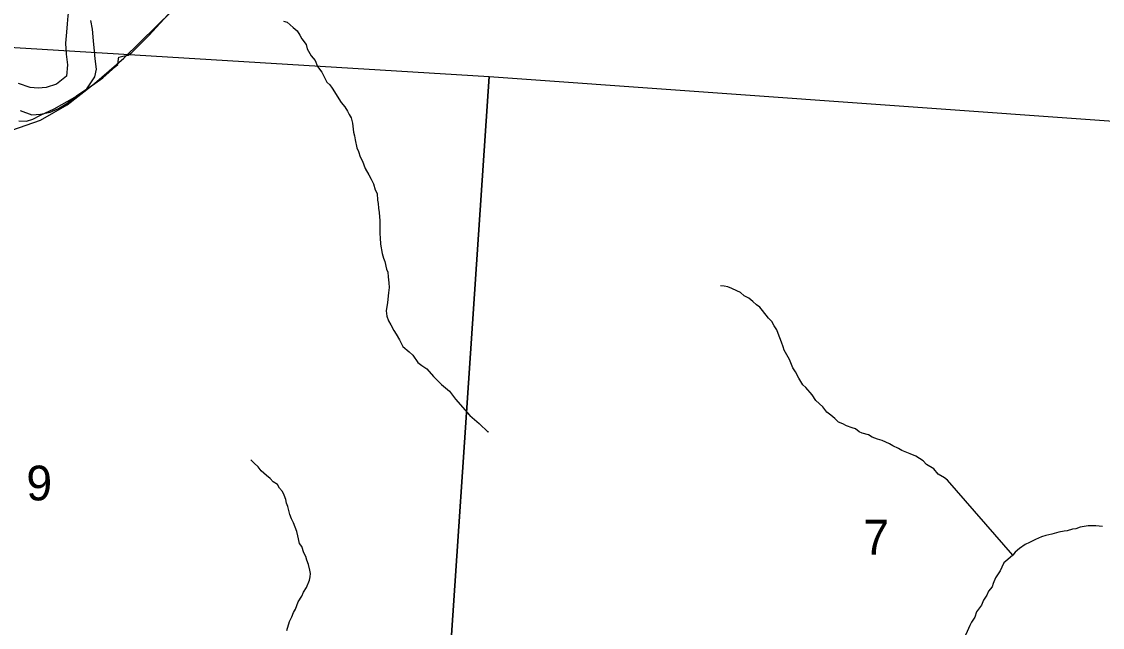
# Model space of a CAD drawing. Extents: x 0 to 44, y -23.8 to 22.
# Drawn here: x 6.018 to 7.321, y 18.843 to 19.573 of the extents above; entities that cross this region are included whole.
import ezdxf

# ---------------------------------------------------------------- set-up
doc = ezdxf.new("R2010")
doc.units = 0
for name, color, linetype in [('GM_X_Minor_River', 7, 'Continuous'), ('GM_X_Rail_Line', 7, 'Continuous'), ('GM_X_Section', 7, 'Continuous'), ('GM_X_Section_Text', 7, 'Continuous'), ('GM_X_Township_Road', 7, 'Continuous')]:
    doc.layers.add(name, color=color, linetype=linetype)

msp = doc.modelspace()

# ---------------------------------------------------------------- linework, layer by layer
at = {"layer": 'GM_X_Minor_River'}
for points in [[(6.0896, 19.6402), (6.0854, 19.6265), (6.0819, 19.617), (6.0781, 19.6045), (6.0758, 19.5942), (6.0739, 19.5802), (6.0732, 19.5706), (6.0724, 19.5604), (6.0712, 19.5471), (6.072, 19.5342), (6.0735, 19.5212), (6.0724, 19.5075), (6.0602, 19.4977), (6.048, 19.4939), (6.0381, 19.4931), (6.0286, 19.4939), (6.0146, 19.4985)], [(6.0164, 19.466), (6.0305, 19.4607), (6.0411, 19.4615), (6.0525, 19.4641), (6.0628, 19.4683), (6.0727, 19.4747), (6.086, 19.485), (6.097, 19.4922), (6.1065, 19.5066), (6.1084, 19.5161), (6.1069, 19.5283), (6.1062, 19.5378), (6.105, 19.55), (6.1039, 19.564), (6.1016, 19.5747)], [(6.3342, 19.5736), (6.3384, 19.5724), (6.3455, 19.5662), (6.3504, 19.562), (6.3537, 19.557), (6.3563, 19.5524), (6.3612, 19.5455), (6.3627, 19.5405), (6.3675, 19.5321), (6.372, 19.5264), (6.3749, 19.5191), (6.3802, 19.5122), (6.3861, 19.5003), (6.3899, 19.4969), (6.3925, 19.493), (6.4036, 19.4758), (6.4078, 19.4704), (6.4111, 19.4651), (6.4133, 19.4612), (6.4156, 19.4574), (6.4174, 19.4509), (6.4184, 19.4399), (6.4195, 19.4357), (6.4206, 19.4308), (6.4224, 19.4209), (6.4246, 19.4166), (6.4264, 19.4102), (6.4294, 19.4048), (6.4323, 19.396), (6.4368, 19.3884), (6.4398, 19.3834), (6.4427, 19.3777), (6.4445, 19.3704), (6.4468, 19.3662), (6.4474, 19.3578), (6.4481, 19.354), (6.4485, 19.3483), (6.4492, 19.343), (6.4502, 19.3331), (6.45, 19.3175), (6.4507, 19.3126), (6.451, 19.305), (6.4531, 19.2936), (6.4546, 19.2882), (6.4561, 19.284), (6.4582, 19.2749), (6.4597, 19.271), (6.4604, 19.2657), (6.4611, 19.2585), (6.4614, 19.2528), (6.4606, 19.2463), (6.4593, 19.2346), (6.458, 19.2247), (6.4587, 19.2182), (6.4605, 19.2125), (6.4635, 19.2075), (6.4669, 19.201), (6.4698, 19.1964), (6.4739, 19.1896), (6.478, 19.1815), (6.4855, 19.175), (6.49, 19.1711)], [(7.2134, 18.9298), (7.1348, 19.0205), (7.131, 19.0232), (7.1235, 19.0278), (7.1182, 19.034), (7.1092, 19.0394), (7.1054, 19.0436), (7.0964, 19.0495), (7.0896, 19.0522), (7.0794, 19.0561), (7.0756, 19.0585), (7.0685, 19.0616), (7.0647, 19.0643), (7.056, 19.0682), (7.0504, 19.0698), (7.0439, 19.0722), (7.0394, 19.0752), (7.0319, 19.0772), (7.0281, 19.0788), (7.0236, 19.0823), (7.0198, 19.0835), (7.013, 19.0858), (7.0085, 19.0882), (7.0032, 19.0905), (6.9987, 19.0948), (6.9938, 19.0986), (6.9893, 19.1025), (6.9844, 19.109), (6.9758, 19.1163), (6.9713, 19.1232), (6.9638, 19.1321), (6.9601, 19.1355), (6.9552, 19.1432), (6.9515, 19.1512), (6.9482, 19.1558), (6.9441, 19.1657), (6.9378, 19.1772), (6.9363, 19.181), (6.9345, 19.1868), (6.9326, 19.1921), (6.9304, 19.1971), (6.929, 19.2017), (6.9256, 19.2066), (6.923, 19.2116), (6.9189, 19.2158), (6.9114, 19.2251), (6.9084, 19.2289), (6.9043, 19.2316), (6.8998, 19.2358), (6.8949, 19.2397), (6.8896, 19.2428), (6.8851, 19.2467), (6.8806, 19.2486), (6.8745, 19.2514), (6.8696, 19.2533), (6.8654, 19.2541), (6.8609, 19.2546)], [(6.49, 19.1711), (6.496, 19.1623), (6.5009, 19.1588), (6.5069, 19.1546), (6.5148, 19.1453), (6.5215, 19.1388), (6.5247, 19.1356)], [(6.5247, 19.1356), (6.5343, 19.1277), (6.5415, 19.1181), (6.5587, 19.0983), (6.57, 19.0887), (6.5806, 19.0784), (6.5813, 19.0795)], [(6.3382, 18.839), (6.3414, 18.85), (6.3441, 18.8557), (6.3461, 18.861), (6.3484, 18.8648), (6.3519, 18.8738), (6.3562, 18.8806), (6.3581, 18.8855), (6.3616, 18.8908), (6.3655, 18.8999), (6.3663, 18.9037), (6.3664, 18.9078), (6.3656, 18.912), (6.3642, 18.9185), (6.362, 18.9239), (6.3609, 18.9284), (6.3587, 18.9326), (6.3561, 18.9403), (6.3535, 18.9441), (6.3513, 18.9532), (6.3499, 18.9586), (6.348, 18.9636), (6.3462, 18.9689), (6.3436, 18.9739), (6.3418, 18.9788), (6.3403, 18.9838), (6.3392, 18.9887), (6.3377, 18.9926), (6.337, 18.9971), (6.3348, 19.0021), (6.333, 19.0067), (6.3292, 19.0109), (6.3266, 19.0151), (6.3217, 19.0182), (6.318, 19.0224), (6.3135, 19.0259), (6.3071, 19.0317), (6.3033, 19.0363), (6.2985, 19.0409), (6.2947, 19.0448)], [(7.3215, 18.9645), (7.3136, 18.9654), (7.309, 18.9655), (7.3041, 18.9655), (7.2946, 18.9637), (7.2893, 18.9619), (7.2855, 18.9612), (7.279, 18.9594), (7.2752, 18.9587), (7.2687, 18.9576), (7.2604, 18.9554), (7.2531, 18.9536), (7.2478, 18.9522), (7.2406, 18.9488), (7.2333, 18.9451), (7.2283, 18.9429), (7.2215, 18.9381), (7.2161, 18.9336), (7.2134, 18.9298), (7.2073, 18.9246), (7.2027, 18.9208), (7.2, 18.9155), (7.198, 18.911), (7.1926, 18.9027), (7.1895, 18.8959), (7.1883, 18.8917), (7.1841, 18.8865), (7.1821, 18.8816), (7.1779, 18.8755), (7.1755, 18.8695), (7.1697, 18.8616)], [(7.1697, 18.8616), (7.1674, 18.8552), (7.1635, 18.8491), (7.1616, 18.8453), (7.1569, 18.8344), (7.1534, 18.8299), (7.1492, 18.825), (7.1457, 18.8186), (7.1388, 18.8088), (7.1334, 18.8039), (7.1288, 18.7983), (7.1226, 18.7919), (7.1184, 18.7874), (7.1172, 18.7813), (7.1118, 18.7768), (7.108, 18.7734), (7.1042, 18.7705)]]:
    msp.add_lwpolyline(points, dxfattribs=at)
at = {"layer": 'GM_X_Rail_Line'}
msp.add_lwpolyline([(6.0065, 19.4423), (6.0411, 19.4544), (6.0732, 19.4729), (6.1062, 19.4986), (6.1416, 19.5292), (6.395, 19.7779), (6.6878, 20.0692), (6.7143, 20.0982), (6.7384, 20.1312), (6.7521, 20.1626), (6.7752, 20.2051), (6.7849, 20.2473), (6.7922, 20.2869), (6.7971, 20.3238), (6.7954, 20.3554), (6.7929, 20.385), (6.7849, 20.432), (6.7699, 20.4736), (6.7338, 20.5421), (6.7166, 20.5611)], dxfattribs=at)
at = {"layer": 'GM_X_Section'}
for points in [[(5.5628, 19.5693), (6.5821, 19.5069), (6.5134, 18.488), (5.5009, 18.5537)], [(6.5821, 19.5069), (7.5875, 19.4351), (7.5123, 18.4238), (6.5134, 18.488)]]:
    msp.add_lwpolyline(points, close=True, dxfattribs=at)
at = {"layer": 'GM_X_Township_Road'}
for points in [[(6.1316, 19.519), (6.1344, 19.5215), (6.1349, 19.5283), (6.1356, 19.5304), (6.1403, 19.5317), (6.1467, 19.5329), (6.151, 19.536), (6.1717, 19.5565), (6.199, 19.5864)], [(6.0151, 19.4538), (6.0242, 19.4533), (6.0319, 19.4556), (6.0411, 19.4606), (6.0575, 19.4681), (6.0826, 19.4821), (6.1065, 19.4986), (6.116, 19.5053), (6.1316, 19.519)]]:
    msp.add_lwpolyline(points, dxfattribs=at)

# ---------------------------------------------------------------- texts
at = {"layer": 'GM_X_Section_Text'}
for s, p in [('9', (6.0239, 18.996)), ('7', (7.0331, 18.9307))]:
    msp.add_text(s, height=0.0419, rotation=0, dxfattribs=at).set_placement(p)

doc.saveas('drawing.dxf')
